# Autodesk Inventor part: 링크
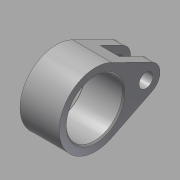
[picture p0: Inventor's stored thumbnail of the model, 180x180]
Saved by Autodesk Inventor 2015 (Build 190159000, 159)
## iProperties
Created: 2016-02
Part Number: 링크
Material: 강철, 연강
Document SubType Name: Modeling
Designer: test
Density: 1 g/cm^3
Appearance: 강철
Author: test
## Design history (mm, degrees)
sketch "스케치1"
  geometry: L1 (20.222, 4.479)-(5.778, 11.645); L2 (20.222, -4.479)-(5.778, -11.645); A1 r 13 centre (0, 0) between (5.778, 11.645) and (5.778, -11.645); A2 r 5 centre (18, 0) between (20.222, -4.479) and (20.222, 4.479); 1 further point
  constraints: 4 end point, 4 point on circle, 4 tangent, 2 centre point, 1 coincident, 1 horizontal alignment
  dimensions: "d0" = 18 distance of point (0, 0) A2.centre; "d1" = 13 radius of A1; "d2" = 5 radius of A2
extrude "돌출1" new body sketch "스케치1" stored distance "d3" = 14; taper "d4" = 0 deg
sketch "스케치2"
  geometry: C1 r 10 at (0, 0); 1 further point
  constraints: 1 centre point, 1 coincident
  dimensions: "d5" = 20 diameter of C1
extrude "돌출2" cut sketch "스케치2" stored distance "d6" = 14; taper "d7" = 0 deg
sketch "스케치3"
  geometry: C1 r 2.5 at (18, 0); A1 r 5 centre (18, 0) between (20.222, -4.479) and (20.222, 4.479) reference; 1 further point
  constraints: 1 centre point, 1 coincident
  dimensions: "d8" = 5 diameter of C1
extrude "돌출3" cut sketch "스케치3" stored distance "d9" = 14; taper "d10" = 0 deg
sketch "스케치4"
  geometry: L1 (20.222, -4.479)-(5.778, -11.645) reference; L2 (5.778, 11.645)-(20.222, 4.479) reference; L3 (12, 8.558)-(12, -8.558); C1 r 2.5 at (18, 0) reference; C2 r 10 at (0, 0) reference; A1 r 13 centre (0, 0) between (5.778, 11.645) and (5.778, -11.645) reference; A2 r 5 centre (18, 0) between (20.222, -4.479) and (20.222, 4.479) reference; 1 further point
  constraints: 2 end point, 2 point on line, 1 vertical
  dimensions: "d11" = 12 distance from line of L3 point (0, 0)
extrude "돌출4" cut sketch "스케치4" stored distance "d12" = 7; taper "d13" = 0 deg
chamfer "모따기1" distance "d14" = 0.5; stored, may be unused: second distance "d15" = 2, angle "d16" = 45 deg
node "솔리드1"
node "절단 모서리 투영1"
